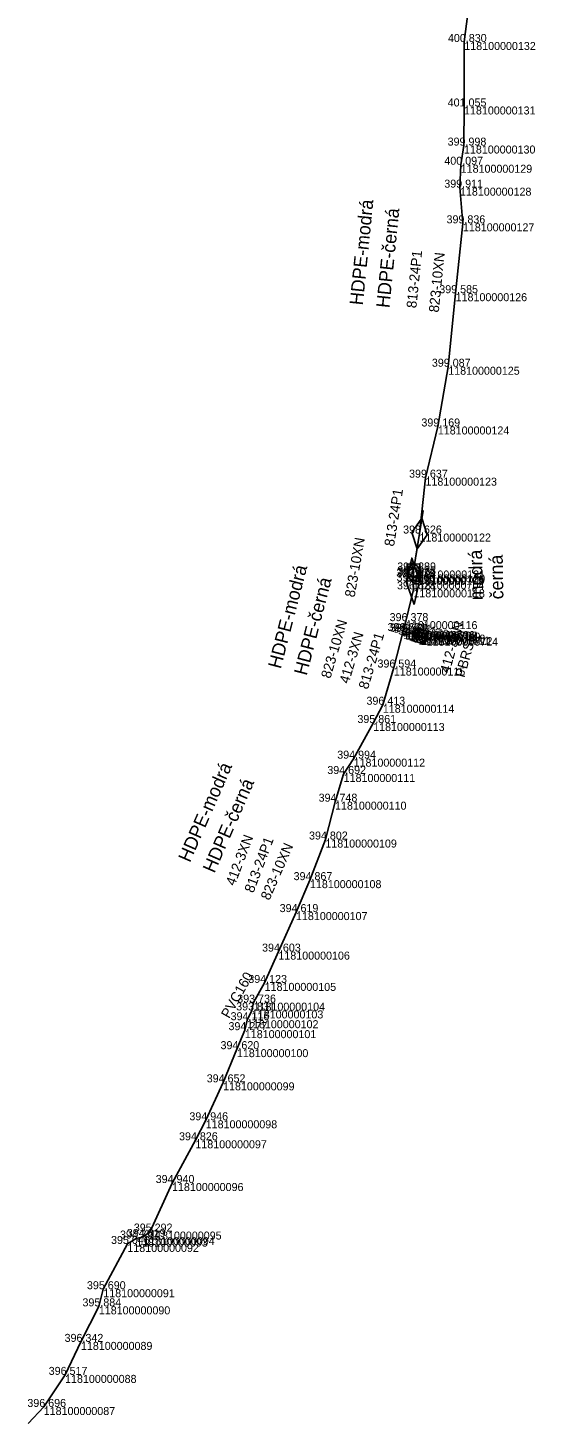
# Model space of a CAD drawing. Extents: x -724084 to -720954, y -948423 to -945131.
# Drawn here: x -721657.4 to -721581.4, y -946985.5 to -946777.4 of the extents above; entities that cross this region are included whole.
import ezdxf

# ---------------------------------------------------------------- set-up
doc = ezdxf.new("R2010")
doc.units = 0
for name, color, linetype in [('Vrstva 27', 7, 'Continuous'), ('Vrstva 28', 7, 'Continuous'), ('Vrstva 3', 7, 'Continuous'), ('Vrstva 31', 7, 'Continuous'), ('Vrstva 33', 7, 'Continuous'), ('Vrstva 35', 7, 'Continuous'), ('Vrstva 60', 7, 'Continuous'), ('Vrstva 61', 7, 'Continuous')]:
    doc.layers.add(name, color=color, linetype=linetype)

msp = doc.modelspace()

# ---------------------------------------------------------------- linework, layer by layer
at = {"layer": 'Vrstva 27'}
msp.add_line((-721600.69, -946868.02), (-721600.67, -946867.92), dxfattribs=at)
msp.add_lwpolyline([(-721600.68, -946867.97), (-721600.28, -946868.1), (-721599.56, -946868.39), (-721598.84, -946868.68), (-721598.49, -946868.77), (-721597.64, -946868.86)], dxfattribs=at)
msp.add_circle((-721600.68, -946867.97), 0.5, dxfattribs=at)
at = {"layer": 'Vrstva 28'}
for p, q in [((-721599.26, -946856.68), (-721598.17, -946849.78)), ((-721599.86, -946853.05), (-721598.35, -946850.93)), ((-721598.35, -946850.93), (-721597.56, -946853.41)), ((-721599.07, -946855.53), (-721599.86, -946853.05)), ((-721597.56, -946853.41), (-721599.07, -946855.53))]:
    msp.add_line(p, q, dxfattribs=at)
for points in [[(-721601.13, -946867.86), (-721600.73, -946866.37), (-721599.62, -946861.6), (-721599.69, -946860.39), (-721599.74, -946859.72), (-721599.65, -946859.59), (-721599.58, -946859.37), (-721599.59, -946858.77), (-721598.71, -946853.23), (-721597.81, -946844.85), (-721595.96, -946837.17), (-721594.4, -946828.21), (-721593.29, -946817.18), (-721592.2, -946806.7), (-721592.64, -946801.35), (-721592.53, -946797.91), (-721592.04, -946795.04), (-721592.03, -946789.17), (-721591.99, -946779.5), (-721591.45, -946775.23)], [(-721657.37, -946986.72), (-721655.02, -946984.24), (-721651.82, -946979.43), (-721649.44, -946974.48), (-721646.76, -946969.15), (-721646.09, -946966.58), (-721642.48, -946959.79), (-721641.14, -946958.98), (-721640.1, -946958.74), (-721639.07, -946957.93), (-721635.79, -946950.65), (-721632.29, -946944.24), (-721630.74, -946941.24), (-721628.14, -946935.55), (-721626.07, -946930.57), (-721624.88, -946927.72), (-721624.55, -946926.23), (-721623.83, -946924.76), (-721623.57, -946923.59), (-721621.91, -946920.64), (-721619.85, -946915.94), (-721617.21, -946910.01), (-721615.12, -946905.22), (-721612.81, -946899.13), (-721611.36, -946893.45), (-721610.07, -946889.3), (-721608.58, -946887), (-721605.65, -946881.65), (-721604.2, -946878.91), (-721602.55, -946873.33), (-721601.13, -946867.86)], [(-721601.13, -946867.86), (-721600.8, -946867.93), (-721600.68, -946867.97)]]:
    msp.add_lwpolyline(points, dxfattribs=at)
at = {"layer": 'Vrstva 3'}
for p, q in [((-721599.73, -946868.89), (-721599.44, -946869.39)), ((-721599.59, -946868.38), (-721598.93, -946869.54)), ((-721599.44, -946867.87), (-721598.42, -946869.68)), ((-721599.3, -946867.36), (-721597.91, -946869.82)), ((-721598.79, -946867.5), (-721597.77, -946869.31)), ((-721598.28, -946867.64), (-721597.63, -946868.8)), ((-721597.77, -946867.79), (-721597.48, -946868.29))]:
    msp.add_line(p, q, dxfattribs=at)
msp.add_lwpolyline([(-721597.37, -946867.9), (-721597.91, -946869.82), (-721599.84, -946869.29), (-721599.3, -946867.36)], close=True, dxfattribs=at)
at = {"layer": 'Vrstva 31'}
for points in [[(-721657.37, -946986.72), (-721655.02, -946984.24), (-721651.82, -946979.43), (-721649.44, -946974.48), (-721646.76, -946969.15), (-721646.09, -946966.58), (-721642.48, -946959.79), (-721641.14, -946958.98), (-721640.1, -946958.74), (-721639.07, -946957.93), (-721635.79, -946950.65), (-721632.29, -946944.24), (-721630.74, -946941.24), (-721628.14, -946935.55), (-721626.07, -946930.57), (-721624.88, -946927.72), (-721624.55, -946926.23), (-721623.83, -946924.76), (-721623.57, -946923.59), (-721621.91, -946920.64), (-721619.85, -946915.94), (-721617.21, -946910.01), (-721615.12, -946905.22), (-721612.81, -946899.13), (-721611.36, -946893.45), (-721610.07, -946889.3), (-721608.58, -946887), (-721605.65, -946881.65), (-721604.2, -946878.91), (-721602.55, -946873.33), (-721601.13, -946867.86), (-721600.73, -946866.37), (-721599.62, -946861.6), (-721599.69, -946860.39), (-721599.74, -946859.72), (-721599.65, -946859.59), (-721599.58, -946859.37), (-721599.59, -946858.77), (-721598.71, -946853.23), (-721597.81, -946844.85), (-721595.96, -946837.17), (-721594.4, -946828.21), (-721593.29, -946817.18), (-721592.2, -946806.7), (-721592.64, -946801.35), (-721592.53, -946797.91), (-721592.04, -946795.04), (-721592.03, -946789.17), (-721591.99, -946779.5), (-721591.45, -946775.23)], [(-721599.51, -946863.89), (-721600.68, -946860.44), (-721599.87, -946856.9), (-721598.69, -946860.34), (-721599.51, -946863.89)]]:
    msp.add_lwpolyline(points, dxfattribs=at)
at = {"layer": 'Vrstva 33'}
msp.add_lwpolyline([(-721657.37, -946986.72), (-721655.02, -946984.24), (-721651.82, -946979.43), (-721649.44, -946974.48), (-721646.76, -946969.15), (-721646.09, -946966.58), (-721642.48, -946959.79), (-721641.14, -946958.98), (-721640.1, -946958.74), (-721639.07, -946957.93), (-721635.79, -946950.65), (-721632.29, -946944.24), (-721630.74, -946941.24), (-721628.14, -946935.55), (-721626.07, -946930.57), (-721624.88, -946927.72), (-721624.55, -946926.23), (-721623.83, -946924.76), (-721623.57, -946923.59), (-721621.91, -946920.64), (-721619.85, -946915.94), (-721617.21, -946910.01), (-721615.12, -946905.22), (-721612.81, -946899.13), (-721611.36, -946893.45), (-721610.07, -946889.3), (-721608.58, -946887), (-721605.65, -946881.65), (-721604.2, -946878.91), (-721602.55, -946873.33), (-721601.13, -946867.86), (-721600.73, -946866.37), (-721599.62, -946861.6), (-721599.69, -946860.39), (-721599.65, -946859.59), (-721599.58, -946859.37), (-721599.59, -946858.77), (-721598.71, -946853.23), (-721597.81, -946844.85), (-721595.96, -946837.17), (-721594.4, -946828.21), (-721593.29, -946817.18), (-721592.2, -946806.7), (-721592.64, -946801.35), (-721592.53, -946797.91), (-721592.04, -946795.04), (-721592.03, -946789.17), (-721591.99, -946779.5), (-721591.45, -946775.23)], dxfattribs=at)
for points in [[(-721598.61, -946859.71), (-721598.64, -946857.79), (-721600.56, -946857.82), (-721600.53, -946859.74)], [(-721598.6, -946860.31), (-721598.63, -946858.39), (-721600.55, -946858.43), (-721600.52, -946860.35)]]:
    msp.add_lwpolyline(points, close=True, dxfattribs=at)
for centre in [(-721599.59, -946858.77), (-721599.58, -946859.37)]:
    msp.add_circle(centre, 0.864, dxfattribs=at)
at = {"layer": 'Vrstva 35'}
msp.add_lwpolyline([(-721624.88, -946927.72), (-721624.55, -946926.23), (-721623.83, -946924.76), (-721623.57, -946923.59), (-721621.91, -946920.64)], dxfattribs=at)
at = {"layer": 'Vrstva 60'}
for p, q in [((-721591.99, -946779.5), (-721591.99, -946779.5)), ((-721592.03, -946789.17), (-721592.03, -946789.17)), ((-721592.04, -946795.04), (-721592.04, -946795.04)), ((-721592.53, -946797.91), (-721592.53, -946797.91)), ((-721592.64, -946801.35), (-721592.64, -946801.35)), ((-721592.2, -946806.7), (-721592.2, -946806.7)), ((-721593.29, -946817.18), (-721593.29, -946817.18)), ((-721594.4, -946828.21), (-721594.4, -946828.21)), ((-721595.96, -946837.17), (-721595.96, -946837.17)), ((-721597.81, -946844.85), (-721597.81, -946844.85)), ((-721598.71, -946853.23), (-721598.71, -946853.23)), ((-721599.59, -946858.77), (-721599.59, -946858.77)), ((-721599.74, -946859.72), (-721599.74, -946859.72)), ((-721599.69, -946860.39), (-721599.69, -946860.39)), ((-721599.65, -946859.59), (-721599.65, -946859.59)), ((-721599.58, -946859.37), (-721599.58, -946859.37)), ((-721599.62, -946861.6), (-721599.62, -946861.6)), ((-721600.73, -946866.37), (-721600.73, -946866.37)), ((-721601.13, -946867.86), (-721601.13, -946867.86)), ((-721600.8, -946867.93), (-721600.8, -946867.93)), ((-721600.68, -946867.97), (-721600.68, -946867.97)), ((-721600.28, -946868.1), (-721600.28, -946868.1)), ((-721599.56, -946868.39), (-721599.56, -946868.39)), ((-721598.84, -946868.68), (-721598.84, -946868.68)), ((-721598.49, -946868.77), (-721598.49, -946868.77)), ((-721597.64, -946868.86), (-721597.64, -946868.86)), ((-721602.55, -946873.33), (-721602.55, -946873.33)), ((-721604.2, -946878.91), (-721604.2, -946878.91)), ((-721605.65, -946881.65), (-721605.65, -946881.65)), ((-721608.58, -946887), (-721608.58, -946887)), ((-721610.07, -946889.3), (-721610.07, -946889.3)), ((-721611.36, -946893.45), (-721611.36, -946893.45)), ((-721612.81, -946899.13), (-721612.81, -946899.13)), ((-721615.12, -946905.22), (-721615.12, -946905.22)), ((-721617.21, -946910.01), (-721617.21, -946910.01)), ((-721619.85, -946915.94), (-721619.85, -946915.94)), ((-721621.91, -946920.64), (-721621.91, -946920.64)), ((-721623.83, -946924.76), (-721623.83, -946924.76)), ((-721623.57, -946923.59), (-721623.57, -946923.59)), ((-721624.55, -946926.23), (-721624.55, -946926.23)), ((-721624.88, -946927.72), (-721624.88, -946927.72)), ((-721626.07, -946930.57), (-721626.07, -946930.57)), ((-721628.14, -946935.55), (-721628.14, -946935.55)), ((-721630.74, -946941.24), (-721630.74, -946941.24)), ((-721632.29, -946944.24), (-721632.29, -946944.24)), ((-721635.79, -946950.65), (-721635.79, -946950.65)), ((-721639.07, -946957.93), (-721639.07, -946957.93)), ((-721642.48, -946959.79), (-721642.48, -946959.79)), ((-721641.14, -946958.98), (-721641.14, -946958.98)), ((-721640.1, -946958.74), (-721640.1, -946958.74)), ((-721646.09, -946966.58), (-721646.09, -946966.58)), ((-721646.76, -946969.15), (-721646.76, -946969.15)), ((-721649.44, -946974.48), (-721649.44, -946974.48)), ((-721651.82, -946979.43), (-721651.82, -946979.43)), ((-721655.02, -946984.24), (-721655.02, -946984.24))]:
    msp.add_line(p, q, dxfattribs=at)

# ---------------------------------------------------------------- texts
at = {"layer": 'Vrstva 27'}
msp.add_text('PBRS6', height=1.5, rotation=74.421, dxfattribs=at).set_placement((-721591.97, -946874.93))
at = {"layer": 'Vrstva 28'}
for s, rotation, p in [('813-24P1', 84.2205, (-721599.18, -946819.48)), ('813-24P1', 81.013, (-721602.52, -946855.23)), ('412-3XN', 74.421, (-721594.23, -946874.29)), ('412-3XN', 73.5166, (-721609.31, -946875.84)), ('813-24P1', 73.5166, (-721606.44, -946876.69)), ('412-3XN', 69.2658, (-721626.4, -946906.17)), ('813-24P1', 69.2658, (-721623.6, -946907.23))]:
    msp.add_text(s, height=1.5, rotation=rotation, dxfattribs=at).set_placement(p)
at = {"layer": 'Vrstva 31'}
for rotation, p in [(84.2205, (-721595.83, -946820.12)), (80.1235, (-721608.44, -946862.87)), (73.5166, (-721612.07, -946875.07)), (66.4183, (-721621.21, -946908.35))]:
    msp.add_text('823-10XN', height=1.5, rotation=rotation, dxfattribs=at).set_placement(p)
at = {"layer": 'Vrstva 33'}
for s, rotation, p in [('HDPE-modrá', 84.2205, (-721607.2, -946819.05)), ('HDPE-černá', 84.2205, (-721603.22, -946819.46)), ('modrá', 91.0451, (-721589.21, -946863.22)), ('černá', 91.0451, (-721586.12, -946863.08)), ('HDPE-modrá', 75.4466, (-721619.5, -946873.62)), ('HDPE-černá', 75.4466, (-721615.62, -946874.62)), ('HDPE-modrá', 66.4183, (-721633.11, -946902.68)), ('HDPE-černá', 66.4183, (-721629.44, -946904.28))]:
    msp.add_text(s, height=2, rotation=rotation, dxfattribs=at).set_placement(p)
at = {"layer": 'Vrstva 35'}
msp.add_text('PVC160', height=1.5, rotation=60.6864, dxfattribs=at).set_placement((-721627.23, -946926.07))
at = {"layer": 'Vrstva 60'}
for s, p in [('118100000132', (-721591.99, -946780.7)), ('118100000131', (-721592.03, -946790.37)), ('118100000130', (-721592.04, -946796.23)), ('118100000129', (-721592.53, -946799.11)), ('118100000128', (-721592.64, -946802.55)), ('118100000127', (-721592.2, -946807.9)), ('118100000126', (-721593.29, -946818.38)), ('118100000125', (-721594.4, -946829.41)), ('118100000124', (-721595.96, -946838.37)), ('118100000123', (-721597.81, -946846.05)), ('118100000122', (-721598.71, -946854.43)), ('118100000121', (-721599.59, -946859.97)), ('118100000119', (-721599.74, -946860.92)), ('118100000704', (-721599.69, -946861.59)), ('118100000705', (-721599.65, -946860.79)), ('118100000120', (-721599.58, -946860.57)), ('118100000118', (-721599.62, -946862.8)), ('118100000116', (-721600.73, -946867.57)), ('118100000706', (-721601.13, -946869.06)), ('118100000707', (-721600.8, -946869.13)), ('118100000708', (-721600.68, -946869.17)), ('118100000709', (-721600.28, -946869.3)), ('118100000710', (-721599.56, -946869.59)), ('118100000711', (-721598.84, -946869.88)), ('118100000712', (-721598.49, -946869.97)), ('118100000714', (-721597.64, -946870.06)), ('118100000115', (-721602.55, -946874.53)), ('118100000114', (-721604.2, -946880.11)), ('118100000113', (-721605.65, -946882.85)), ('118100000112', (-721608.58, -946888.2)), ('118100000111', (-721610.07, -946890.5)), ('118100000110', (-721611.36, -946894.65)), ('118100000109', (-721612.81, -946900.33)), ('118100000108', (-721615.12, -946906.42)), ('118100000107', (-721617.21, -946911.21)), ('118100000106', (-721619.85, -946917.14)), ('118100000105', (-721621.91, -946921.83)), ('118100000103', (-721623.83, -946925.96)), ('118100000104', (-721623.57, -946924.8)), ('118100000102', (-721624.55, -946927.43)), ('118100000101', (-721624.88, -946928.92)), ('118100000100', (-721626.07, -946931.77)), ('118100000099', (-721628.14, -946936.75)), ('118100000098', (-721630.74, -946942.44)), ('118100000097', (-721632.29, -946945.44)), ('118100000096', (-721635.79, -946951.85)), ('118100000095', (-721639.07, -946959.13)), ('118100000092', (-721642.48, -946960.99)), ('118100000093', (-721641.14, -946960.18)), ('118100000094', (-721640.1, -946959.94)), ('118100000091', (-721646.09, -946967.78)), ('118100000090', (-721646.76, -946970.35)), ('118100000089', (-721649.44, -946975.68)), ('118100000088', (-721651.82, -946980.63)), ('118100000087', (-721655.02, -946985.45))]:
    msp.add_text(s, height=1.2, dxfattribs=at).set_placement(p)
at = {"layer": 'Vrstva 61'}
for s, p in [('400.830', (-721594.44, -946779.5)), ('401.055', (-721594.48, -946789.17)), ('399.998', (-721594.49, -946795.04)), ('400.097', (-721594.98, -946797.91)), ('399.911', (-721594.99, -946801.35)), ('399.836', (-721594.65, -946806.7)), ('399.585', (-721595.74, -946817.18)), ('399.087', (-721596.85, -946828.21)), ('399.169', (-721598.42, -946837.17)), ('399.637', (-721600.27, -946844.85)), ('398.626', (-721601.16, -946853.23)), ('396.973', (-721602.19, -946859.72)), ('397.289', (-721602.04, -946858.77)), ('397.078', (-721602.03, -946859.37)), ('397.261', (-721602.01, -946859.59)), ('396.866', (-721602.14, -946860.39)), ('396.628', (-721602.08, -946861.6)), ('396.631', (-721603.49, -946867.86)), ('396.378', (-721603.18, -946866.37)), ('396.781', (-721603.15, -946867.93)), ('397.881', (-721603.04, -946867.97)), ('397.641', (-721602.64, -946868.1)), ('398.071', (-721601.92, -946868.39)), ('398.180', (-721601.29, -946868.68)), ('398.203', (-721600.95, -946868.77)), ('398.490', (-721600.09, -946868.86)), ('396.594', (-721605, -946873.33)), ('396.413', (-721606.65, -946878.91)), ('395.861', (-721608.01, -946881.65)), ('394.994', (-721611.03, -946887)), ('394.692', (-721612.52, -946889.3)), ('394.748', (-721613.82, -946893.45)), ('394.802', (-721615.26, -946899.13)), ('394.867', (-721617.57, -946905.22)), ('394.619', (-721619.66, -946910.01)), ('394.603', (-721622.3, -946915.94)), ('394.123', (-721624.36, -946920.64)), ('393.736', (-721626.02, -946923.59)), ('394.116', (-721627.01, -946926.23)), ('393.831', (-721626.18, -946924.76)), ('394.277', (-721627.33, -946927.72)), ('394.620', (-721628.52, -946930.57)), ('394.652', (-721630.59, -946935.55)), ('394.946', (-721633.19, -946941.24)), ('394.826', (-721634.74, -946944.24)), ('394.940', (-721638.24, -946950.65)), ('395.046', (-721644.93, -946959.79)), ('394.797', (-721643.59, -946958.98)), ('394.819', (-721642.56, -946958.74)), ('395.292', (-721641.52, -946957.93)), ('395.690', (-721648.54, -946966.58)), ('395.884', (-721649.21, -946969.15)), ('396.342', (-721651.89, -946974.48)), ('396.517', (-721654.27, -946979.43)), ('396.696', (-721657.47, -946984.24))]:
    msp.add_text(s, height=1.2, dxfattribs=at).set_placement(p)

doc.saveas('drawing.dxf')
